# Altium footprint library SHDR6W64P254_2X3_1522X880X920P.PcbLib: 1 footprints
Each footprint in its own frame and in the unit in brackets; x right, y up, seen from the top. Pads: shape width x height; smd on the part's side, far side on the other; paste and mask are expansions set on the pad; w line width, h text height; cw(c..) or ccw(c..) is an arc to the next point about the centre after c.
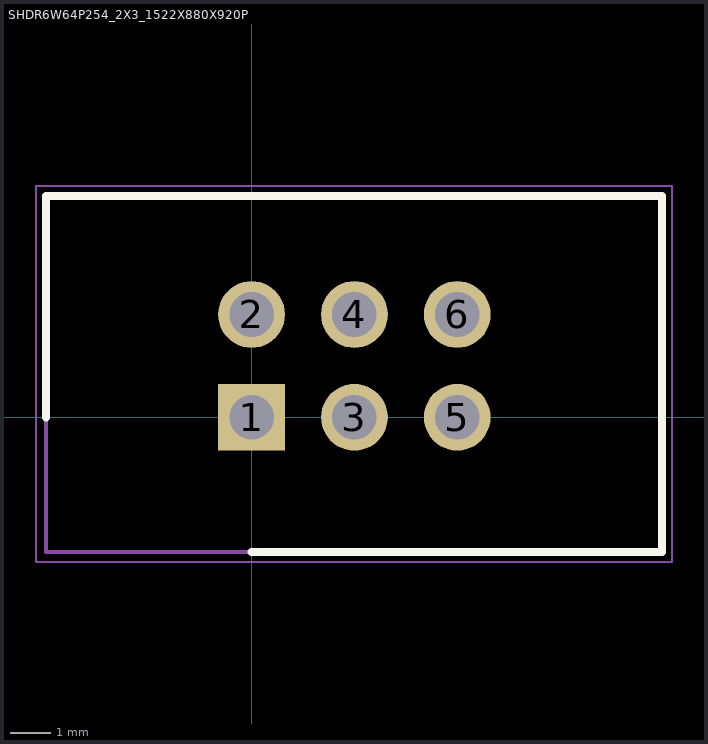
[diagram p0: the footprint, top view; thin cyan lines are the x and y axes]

## SHDR6W64P254_2X3_1522X880X920P [mm]
pads (6):
  rect 1.65x1.65 / inner round 1.65 / far side rect 1.65x1.65 hole 1.1: 1(0,0)
  round 1.65 hole 1.1: 2(0,2.54) 3(2.54,0) 4(2.54,2.54) 5(5.08,0) 6(5.08,2.54)
Top Overlay:
  lines w0.2: -5.08,0 -5.08,5.47 10.14,5.47 10.14,-3.33 0,-3.33
Mechanical 15:
  lines w0.1: -5.08,-3.33 -5.08,5.47 10.14,5.47 10.14,-3.33 -5.08,-3.33
Mechanical 20:
  lines w0.05: -5.33,-3.58 -5.33,5.72 10.39,5.72 10.39,-3.58 -5.33,-3.58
